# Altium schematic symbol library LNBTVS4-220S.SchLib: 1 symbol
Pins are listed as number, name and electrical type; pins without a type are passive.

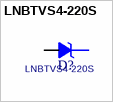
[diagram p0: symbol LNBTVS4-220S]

## LNBTVS4-220S
designator D?
footprint ST_SMC
pins: 1 K, 2 A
